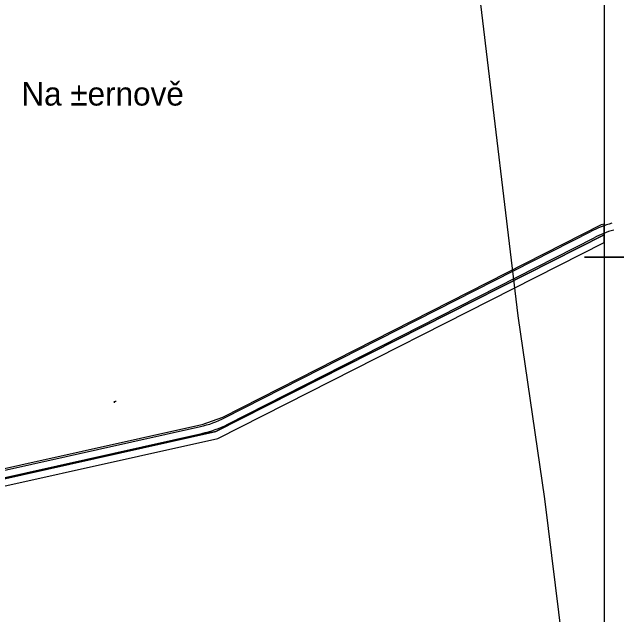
# Model space of a CAD drawing. Extents: x -574342 to -507939, y -1144044 to -1123894.
# Drawn here: x -508278.2 to -508018.5, y -1143296.5 to -1143040.7 of the extents above; entities that cross this region are included whole.
import ezdxf

# ---------------------------------------------------------------- set-up
doc = ezdxf.new("R2010")
doc.units = 0
for name, color, linetype in [('01_MÍSTNÍ_NÁZVY', 7, 'Continuous'), ('01_PARCELY_NAVRH_PC', 7, 'Continuous'), ('01_PARCELY_NAVRH_ŽP', 7, 'Continuous'), ('42', 7, 'Continuous'), ('43', 7, 'Continuous'), ('cesty', 7, 'Continuous'), ('Level 1', 7, 'Continuous')]:
    doc.layers.add(name, color=color, linetype=linetype)

msp = doc.modelspace()

# ---------------------------------------------------------------- linework, layer by layer
msp.add_lwpolyline([(-508035.07, -1143144.7), (-508035.07, -1143144.7), (-508018.45, -1143144.7), (-508018.45, -1143144.7)], close=True)
msp.add_lwpolyline([(-508035.07, -1143144.7), (-508035.07, -1143144.7), (-508018.45, -1143144.7), (-508018.45, -1143144.7)], close=True)
at = {"layer": '01_PARCELY_NAVRH_PC'}
msp.add_line((-508026.76, -1143135.13), (-508026.76, -1143130.62), dxfattribs=at)
msp.add_lwpolyline([(-508026.76, -1143130.62), (-508028.05, -1143130.95), (-508188.91, -1143212.74), (-508197.69, -1143215.86), (-508325.49, -1143244.3), (-508415.56, -1143252.78), (-508417.38, -1143252.95), (-508420.04, -1143252.1), (-508422.7, -1143249.88), (-508420.08, -1143265.35), (-508419.24, -1143259.91), (-508414.23, -1143256.72), (-508401.25, -1143255.47), (-508381.42, -1143253.61), (-508325.37, -1143248.48), (-508191.76, -1143218.68), (-508026.76, -1143135.13)], dxfattribs=at)
at = {"layer": '01_PARCELY_NAVRH_ŽP'}
msp.add_line((-508026.76, -1143138.46), (-508026.76, -1143135.13), dxfattribs=at)
msp.add_lwpolyline([(-508026.76, -1143135.13), (-508191.76, -1143218.68), (-508325.37, -1143248.48), (-508381.42, -1143253.61), (-508387.45, -1143257.24), (-508324.47, -1143251.4), (-508190.87, -1143221.6), (-508026.76, -1143138.46)], dxfattribs=at)
at = {"layer": '42'}
msp.add_lwpolyline([(-508089.09, -1142959.05), (-508078.85, -1143040.72), (-508063.44, -1143169.52), (-508052.19, -1143247.27), (-508038.7, -1143356.14), (-508026.76, -1143440.84)], dxfattribs=at)
msp.add_lwpolyline([(-508089.09, -1142959.05), (-508078.85, -1143040.72), (-508063.44, -1143169.52), (-508052.19, -1143247.27), (-508038.7, -1143356.14), (-508026.76, -1143440.84)], dxfattribs=at)
at = {"layer": '43'}
for points in [[(-508234.75, -1143206.53), (-508234.75, -1143205.8)], [(-508234.75, -1143206.04), (-508234.64, -1143205.94), (-508234.54, -1143205.88), (-508234.38, -1143205.83), (-508234.23, -1143205.81), (-508234.08, -1143205.8)]]:
    msp.add_lwpolyline(points, dxfattribs=at)
at = {"layer": 'cesty'}
for p, q in [((-508188.02, -1143212.87), (-508032.44, -1143133.72)), ((-508186.66, -1143215.54), (-508031.08, -1143136.39)), ((-508322.93, -1143244.32), (-508198.29, -1143216.56)), ((-508322.28, -1143247.25), (-508197.63, -1143219.48))]:
    msp.add_line(p, q, dxfattribs=at)
for centre, radius, start, end in [((-508011.36, -1143175.17), 46.5, 105.1463, 116.9636), ((-508011.36, -1143175.17), 43.5, 105.1463, 116.9636), ((-508207.74, -1143174.1), 43.5, 282.5596, 296.9636), ((-508207.74, -1143174.1), 46.5, 282.5596, 296.9636)]:
    msp.add_arc(centre, radius, start, end, dxfattribs=at)
at = {"layer": 'Level 1'}
msp.add_lwpolyline([(-508026.76, -1142847.7), (-508026.76, -1144035.7), (-508866.76, -1144035.7), (-508866.76, -1142847.7)], close=True, dxfattribs=at)

# ---------------------------------------------------------------- texts
at = {"layer": '01_MÍSTNÍ_NÁZVY'}
msp.add_text('Na ±ernově', height=10, dxfattribs=at).set_placement((-508274.34, -1143080.29))

doc.saveas('drawing.dxf')
